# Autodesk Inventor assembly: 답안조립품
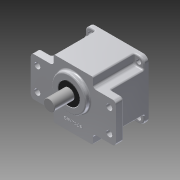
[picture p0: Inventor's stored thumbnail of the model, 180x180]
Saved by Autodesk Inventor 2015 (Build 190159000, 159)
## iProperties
Created: 2014-12
Part Number: 답안조립품
Document SubType Name: Assembly
Designer: 영환
Author: 영환
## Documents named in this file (12)
- C:\Users\영환\Desktop\Inventor2급-주영환\답안조립품.iam
- C:\Users\영환\Desktop\Inventor2급-주영환\본체.ipt
- C:\Users\영환\Desktop\Inventor2급-주영환\커버.ipt
- C:\Users\영환\Desktop\Inventor2급-주영환\메인축.ipt
- C:\Users\영환\Desktop\Inventor2급-주영환\서브축.ipt
- C:\Users\영환\Desktop\Inventor2급-주영환\베어링 608.ipt
- 베어링 608.ipt
- C:\Users\영환\Desktop\Inventor2급-주영환\베어링 6003.ipt
- 베어링 6003.ipt
- C:\Users\영환\Desktop\Inventor2급-주영환\오일실 17x32x8.ipt
- C:\Users\영환\Desktop\Inventor2급-주영환\오일실 8x22x7.ipt
- C:\Users\영환\Desktop\Inventor2급-주영환\M4x0.5x16.ipt
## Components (4 placed, 1 different names)
1. M4x0.5x12:1 — 각도:1
2. M4x0.5x12:2
3. M4x0.5x12:3
4. M4x0.5x12:4
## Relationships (1: Angle 1)
- 각도:1 [Angle]: M4x0.5x12:1
